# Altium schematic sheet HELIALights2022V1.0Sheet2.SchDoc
size A3; SheetNumber: 2; SheetTotal: 2
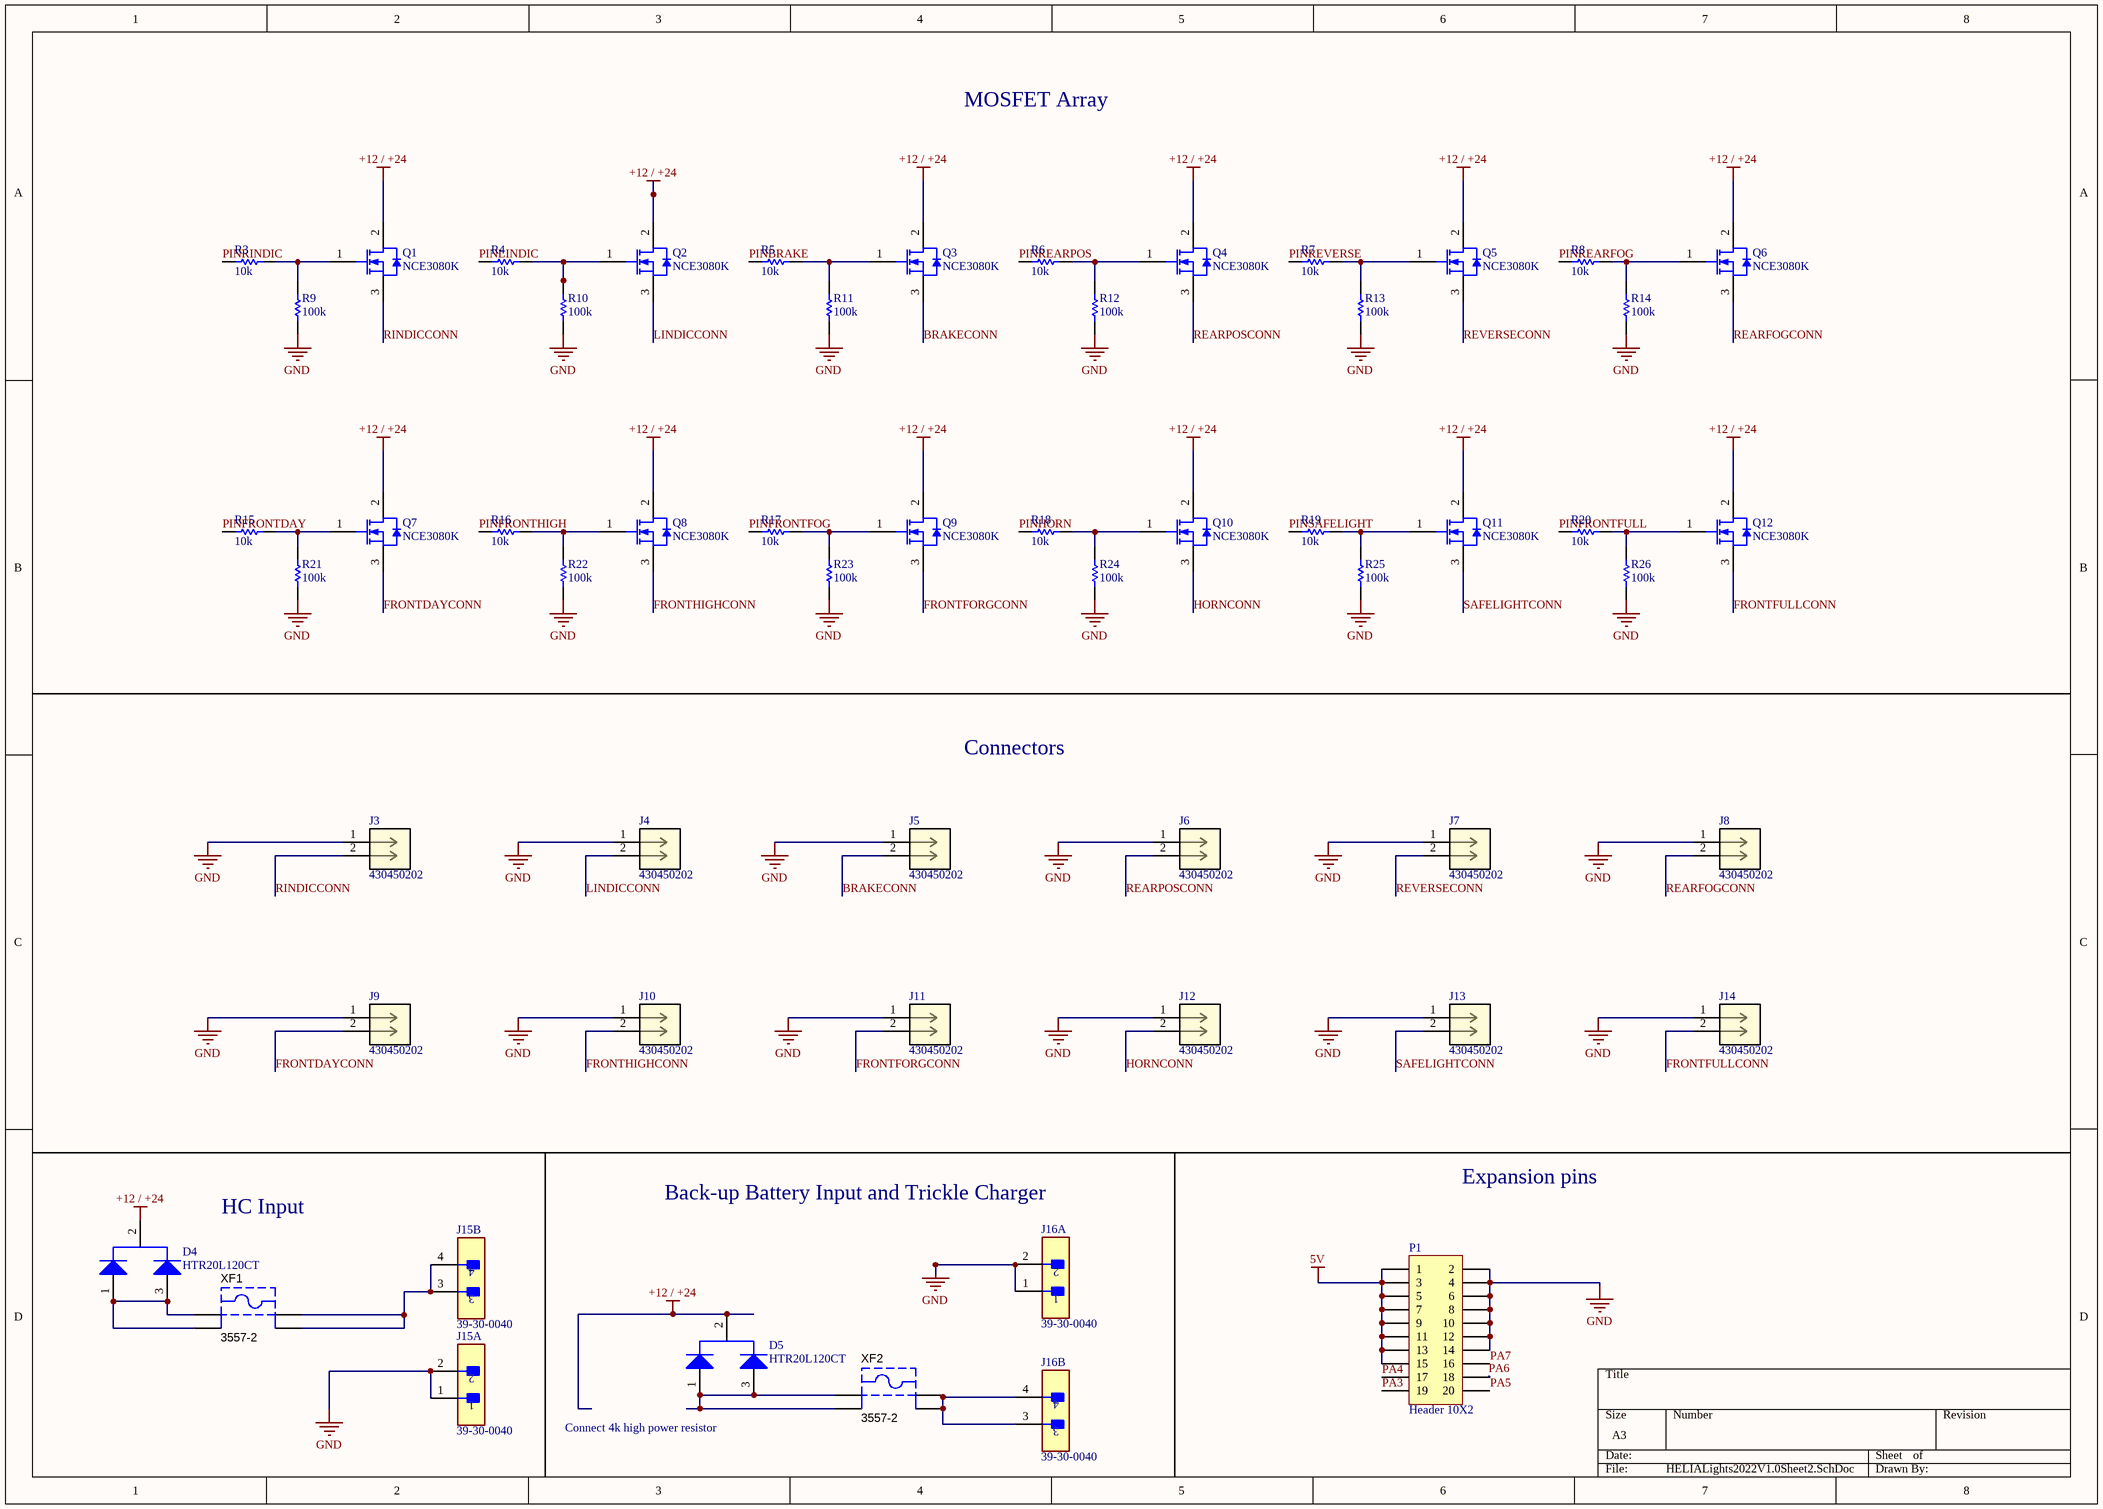
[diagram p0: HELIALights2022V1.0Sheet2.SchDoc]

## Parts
D4  HTR20L120CT  [ONSC-TO-220-3-221A-09]
D5  HTR20L120CT  [ONSC-TO-220-3-221A-09]
J3  430450202  [CON_430450202_MOL]
J4  430450202  [CON_430450202_MOL]
J5  430450202  [CON_430450202_MOL]
J6  430450202  [CON_430450202_MOL]
J7  430450202  [CON_430450202_MOL]
J8  430450202  [CON_430450202_MOL]
J9  430450202  [CON_430450202_MOL]
J10  430450202  [CON_430450202_MOL]
J11  430450202  [CON_430450202_MOL]
J12  430450202  [CON_430450202_MOL]
J13  430450202  [CON_430450202_MOL]
J14  430450202  [CON_430450202_MOL]
J15  39-30-0040  [FP-39-30-0040-MFG]  (parts A,B of 2)
J16  39-30-0040  [FP-39-30-0040-MFG]  (parts A,B of 2)
P1  Header 10X2  [HDR2X10]
Q1  NCE3080K  [INF-PG-TO252-3-313_L]
Q2  NCE3080K  [INF-PG-TO252-3-313_L]
Q3  NCE3080K  [INF-PG-TO252-3-313_L]
Q4  NCE3080K  [INF-PG-TO252-3-313_L]
Q5  NCE3080K  [INF-PG-TO252-3-313_L]
Q6  NCE3080K  [INF-PG-TO252-3-313_L]
Q7  NCE3080K  [INF-PG-TO252-3-313_L]
Q8  NCE3080K  [INF-PG-TO252-3-313_L]
Q9  NCE3080K  [INF-PG-TO252-3-313_L]
Q10  NCE3080K  [INF-PG-TO252-3-313_L]
Q11  NCE3080K  [INF-PG-TO252-3-313_L]
Q12  NCE3080K  [INF-PG-TO252-3-313_L]
R3  10k  [RESC1609X50X30NL8T20]
R4  10k  [RESC1609X50X30NL8T20]
R5  10k  [RESC1609X50X30NL8T20]
R6  10k  [RESC1609X50X30NL8T20]
R7  10k  [RESC1609X50X30NL8T20]
R8  10k  [RESC1609X50X30NL8T20]
R9  100k  [RESC1609X50X30NL8T20]
R10  100k  [RESC1609X50X30NL8T20]
R11  100k  [RESC1609X50X30NL8T20]
R12  100k  [RESC1609X50X30NL8T20]
R13  100k  [RESC1609X50X30NL8T20]
R14  100k  [RESC1609X50X30NL8T20]
R15  10k  [RESC1609X50X30NL8T20]
R16  10k  [RESC1609X50X30NL8T20]
R17  10k  [RESC1609X50X30NL8T20]
R18  10k  [RESC1609X50X30NL8T20]
R19  10k  [RESC1609X50X30NL8T20]
R20  10k  [RESC1609X50X30NL8T20]
R21  100k  [RESC1609X50X30NL8T20]
R22  100k  [RESC1609X50X30NL8T20]
R23  100k  [RESC1609X50X30NL8T20]
R24  100k  [RESC1609X50X30NL8T20]
R25  100k  [RESC1609X50X30NL8T20]
R26  100k  [RESC1609X50X30NL8T20]
XF1  3557-2  [KSTN-3557-2]
XF2  3557-2  [KSTN-3557-2]

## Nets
5V: P1.1 P1.3 P1.5 P1.7 P1.9 P1.11 P1.13 P1.15
+12 / +24: D4.2(K) D5.2(K) Q1.2(DRAIN) Q2.2(DRAIN) Q3.2(DRAIN) Q4.2(DRAIN) Q5.2(DRAIN) Q6.2(DRAIN) Q7.2(DRAIN) Q8.2(DRAIN) Q9.2(DRAIN) Q10.2(DRAIN) Q11.2(DRAIN) Q12.2(DRAIN)
GND: J3.1 J4.1 J5.1 J6.1 J7.1 J8.1 J9.1 J10.1 J11.1 J12.1 J13.1 J14.1 J15.1 J15.2 J16.1 J16.2 P1.2 P1.4 P1.6 P1.8 P1.10 P1.12 P1.14 R9.2 R10.2 R11.2 R12.2 R13.2 R14.2 R21.2 R22.2 R23.2 R24.2 R25.2 R26.2
BRAKECONN: J5.2 Q3.3(SOURCE)
FRONTDAYCONN: J9.2 Q7.3(SOURCE)
FRONTFORGCONN: J11.2 Q9.3(SOURCE)
FRONTFULLCONN: J14.2 Q12.3(SOURCE)
FRONTHIGHCONN: J10.2 Q8.3(SOURCE)
HORNCONN: J12.2 Q10.3(SOURCE)
LINDICCONN: J4.2 Q2.3(SOURCE)
PA3: P1.19
PA4: P1.17
PA5: P1.20
PA6: P1.18
PA7: P1.16
PINBRAKE: R5.2
PINFRONTDAY: R15.2
PINFRONTFOG: R17.2
PINFRONTFULL: R20.2
PINFRONTHIGH: R16.2
PINHORN: R18.2
PINLINDIC: R4.2
PINREARFOG: R8.2
PINREARPOS: R6.2
PINREVERSE: R7.2
PINRINDIC: R3.2
PINSAFELIGHT: R19.2
REARFOGCONN: J8.2 Q6.3(SOURCE)
REARPOSCONN: J6.2 Q4.3(SOURCE)
REVERSECONN: J7.2 Q5.3(SOURCE)
RINDICCONN: J3.2 Q1.3(SOURCE)
SAFELIGHTCONN: J13.2 Q11.3(SOURCE)
NetD4_1: D4.1(A1) D4.3(A2) XF1.1 XF1.2
NetD5_1: D5.1(A1) D5.3(A2) XF2.1 XF2.2
NetJ15_3: J15.3 J15.4 XF1.3 XF1.4
NetJ16_3: J16.3 J16.4 XF2.3 XF2.4
NetQ1_1: Q1.1(GATE) R3.1 R9.1
NetQ2_1: Q2.1(GATE) R4.1 R10.1
NetQ3_1: Q3.1(GATE) R5.1 R11.1
NetQ4_1: Q4.1(GATE) R6.1 R12.1
NetQ5_1: Q5.1(GATE) R7.1 R13.1
NetQ6_1: Q6.1(GATE) R8.1 R14.1
NetQ7_1: Q7.1(GATE) R15.1 R21.1
NetQ8_1: Q8.1(GATE) R16.1 R22.1
NetQ9_1: Q9.1(GATE) R17.1 R23.1
NetQ10_1: Q10.1(GATE) R18.1 R24.1
NetQ11_1: Q11.1(GATE) R19.1 R25.1
NetQ12_1: Q12.1(GATE) R20.1 R26.1

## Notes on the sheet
- MOSFET Array
- Connectors
- Expansion pins
- HC Input
- Back-up Battery Input and Trickle Charger
- Connect 4k high power resistor

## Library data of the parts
D4 D5 = CMP-1055-00618-1: SWITCHMODE(TM) Power Rectifier, 60 V, 30 A, 3-Pin TO-220, Pb-Free, Tube; Manufacturer: On Semiconductor; PartNumber: MBR30H60CTG; Configuration: Common Cathode; IFSM Max (A): 260
J3-J14 = 430450202: No Description Available; Mfr_Name: Molex Connector Corporation
J15 J16 = CMP-2000-05600-2: CONN HEADER R/A 4POS 4.2MM; Manufacturer: Molex; Current Rating: 13A; Voltage Rating: 600V; Number Of Contacts: 4; Standoff Height: 0.4mm; Conn Orientation: Right Angle; Conn Gender: Male
P1 = Header 10X2: Header, 10-Pin, Dual row
Q1-Q12 = CMP-1164-00349-1: N-Channel CoolMOS E6 Power-Transistor, 600 V VDS, 7.3 A ID, -55 to 150 degC, PG-TO252-3-313, Reel, Green; Manufacturer: Infineon; PartNumber: IPD60R600C6; IDpuls (max): 19Â A; VDS (max): 600Â V; VGS(th) (min): 2.5Â V; Ptot (max): 63Â W; Rth: 2Â K/W; VGS(th) (max): 3.5Â V; QG: 20.5Â nC; Green: TRUE; RDS (on) (max): 600Â mOhm; ID (max): 7.3Â A; RthJA (max): 62Â K/W; Polarity: N
R3-R26 = CMP-2000-03816-5: Chip Resistor, 0 Ohm, Jumper, 100 mW, -55 to 155 degC, 0603 (1608 Metric), RoHS, Tape and Reel; Manufacturer: Vishay Semiconductor; Voltage Rating: 75 V
XF1 XF2 = CMP-2000-05461-1: FUSE HOLDER, PCB MOUNT, 500VAC, 20A, ROHS; Manufacturer: Keystone-Electronics; Number of Circuits: 1; Voltage: 500V; Fuseholder Type: Block; Fuse Type: Blade; Fuse Size: 0.43"Lx0.15"Wx0.64"H(10.92mmx3.81mmx16.25mm); For Use With/Related Products: ATC,ATO257,MINI897; Current Rating: 30A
